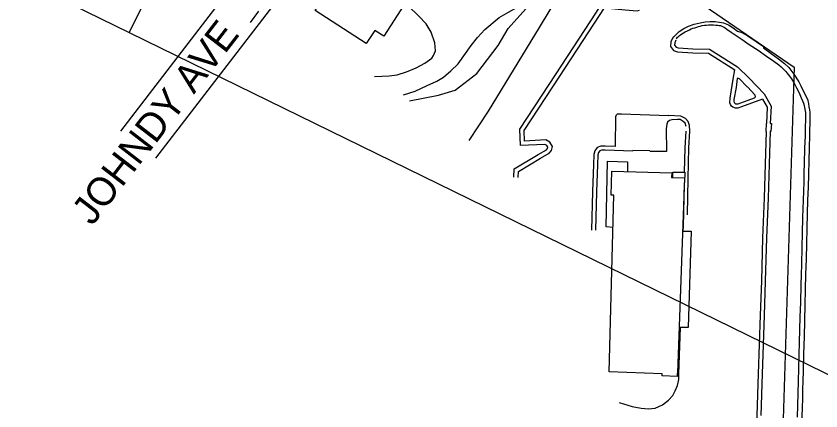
# Model space of a CAD drawing. Extents: x 1517485 to 1521905, y 636528 to 640355.
# Drawn here: x 1519953.2 to 1520407.4, y 637322.6 to 637545.3 of the extents above; entities that cross this region are included whole.
import ezdxf

# ---------------------------------------------------------------- set-up
doc = ezdxf.new("R2010")
doc.units = 0
for name, color, linetype in [('Exist Building', 7, 'Continuous'), ('Exist Building Metal Canopy', 7, 'Continuous'), ('Exist Other Culture Area Outline', 7, 'Continuous'), ('Exist Right of Way Line', 7, 'Continuous'), ('Exist Roads Change in Surface', 7, 'Continuous'), ('Exist Roads Curbs', 7, 'Continuous'), ('Exist Roads EOP', 7, 'Continuous'), ('Exist Roads EOP Other', 7, 'Continuous'), ('Exist Roads EOP Text', 7, 'Continuous'), ('Exist Roads Soil', 7, 'Continuous'), ('Exist Vegetation Woods Line', 7, 'Continuous'), ('Scratch_Level_3', 7, 'Continuous')]:
    doc.layers.add(name, color=color, linetype=linetype)

msp = doc.modelspace()

# ---------------------------------------------------------------- linework, layer by layer
at = {"layer": 'Exist Building'}
for points in [[(1520143.1, 637570.15), (1520171.98, 637551.59), (1520160.69, 637534.02), (1520155.58, 637537.3), (1520150.84, 637529.92), (1520121.89, 637548.53), (1520130.07, 637561.26), (1520135.25, 637557.94)], [(1520287.9, 637344.62), (1520290.55, 637444.38), (1520289.08, 637444.42), (1520289.44, 637457.88), (1520323.16, 637456.9), (1520323.06, 637454.35), (1520330.4, 637454.08), (1520326.36, 637344.18), (1520326.34, 637343.67), (1520326.28, 637342.06), (1520317.73, 637342.38), (1520317.77, 637343.53)]]:
    msp.add_lwpolyline(points, close=True, dxfattribs=at)
at = {"layer": 'Exist Building Metal Canopy'}
for points in [[(1520323.9, 637454.32), (1520323.9, 637457.34), (1520330.6, 637457.25), (1520330.46, 637451.24), (1520330.3, 637451.24)], [(1520329.3, 637424.1), (1520334.13, 637424.11), (1520332.4, 637369.78), (1520327.3, 637369.72)]]:
    msp.add_lwpolyline(points, dxfattribs=at)
at = {"layer": 'Exist Other Culture Area Outline'}
msp.add_lwpolyline([(1520290.07, 637426.12), (1520286.11, 637426.52), (1520286.85, 637463.46), (1520298.27, 637463.2), (1520298.22, 637457.63)], dxfattribs=at)
at = {"layer": 'Exist Right of Way Line'}
for p, q in [((1520138.34, 637644.64), (1520012.02, 637480.39)), ((1520158.15, 637629.4), (1520031.83, 637465.15)), ((1520245.65, 637617.28), (1520392.38, 637516.53)), ((1520392.38, 637516.53), (1520383.93, 637249.27))]:
    msp.add_line(p, q, dxfattribs=at)
at = {"layer": 'Exist Roads Change in Surface'}
msp.add_lwpolyline([(1520291.41, 637471.78), (1520291.7, 637488.65), (1520292.02, 637489.56), (1520292.53, 637490.21), (1520294.79, 637490.22), (1520321.33, 637489.25)], dxfattribs=at)
at = {"layer": 'Exist Roads Curbs'}
for points in [[(1520234.02, 637454.46), (1520234.33, 637459.2), (1520247.91, 637467.24), (1520252.43, 637469.91), (1520253.01, 637470.68), (1520253.22, 637471.48), (1520252.65, 637472.39), (1520251.6, 637472.97), (1520237.79, 637472.27), (1520237.48, 637481.58), (1520254.01, 637506.71), (1520267.89, 637527.96), (1520280.3, 637547.04), (1520283.92, 637552.69), (1520297.21, 637551.26), (1520303.37, 637550.74), (1520303.81, 637550.9)], [(1520325.69, 637532.47), (1520326.04, 637532.92), (1520326.47, 637533.4), (1520326.96, 637533.86), (1520327.53, 637534.33), (1520328.17, 637534.81), (1520328.89, 637535.32), (1520329.78, 637535.86), (1520330.85, 637536.44), (1520332, 637537.05), (1520333.2, 637537.67), (1520334.24, 637538.15), (1520335.15, 637538.48), (1520336.16, 637538.82), (1520337.29, 637539.18), (1520338.33, 637539.49), (1520339.29, 637539.75), (1520340.39, 637539.97), (1520341.63, 637540.16), (1520342.81, 637540.29), (1520343.9, 637540.37), (1520344.85, 637540.42), (1520345.72, 637540.43), (1520346.8, 637540.39), (1520348.07, 637540.29), (1520349.18, 637540.18), (1520350.05, 637540.07), (1520350.69, 637539.98), (1520351.14, 637539.89), (1520351.53, 637539.76), (1520351.91, 637539.57), (1520352.26, 637539.35), (1520352.76, 637539.02), (1520354.25, 637538.02), (1520356.77, 637536.33), (1520359.64, 637534.39), (1520362.85, 637532.22), (1520366.97, 637529.42), (1520371.91, 637526.05), (1520376.64, 637522.8), (1520380.83, 637519.88), (1520383.57, 637517.88), (1520384.91, 637516.76), (1520385.94, 637515.81), (1520386.84, 637514.9), (1520387.6, 637514.09), (1520388.24, 637513.35), (1520388.93, 637512.48), (1520389.71, 637511.41), (1520390.69, 637509.95), (1520391.83, 637508.13), (1520392.81, 637506.43), (1520393.62, 637504.87), (1520394.5, 637503.11), (1520395.47, 637501.14), (1520396.3, 637499.3), (1520396.96, 637497.64), (1520397.49, 637496.21), (1520397.89, 637494.98), (1520398.19, 637493.86), (1520398.4, 637492.84), (1520398.55, 637491.88), (1520398.64, 637490.97), (1520398.68, 637490.01), (1520398.67, 637488.86), (1520398.63, 637486.56), (1520398.55, 637482.94), (1520398.41, 637477.73), (1520398.21, 637470.87), (1520397.97, 637462.14), (1520397.82, 637457.06), (1520397.67, 637451.78), (1520397.52, 637446.59), (1520397.37, 637441.5), (1520397.07, 637431.68), (1520396.82, 637422.98), (1520396.63, 637415.06), (1520396.38, 637405.29), (1520396.23, 637399.54), (1520396.08, 637393.77), (1520395.8, 637383.77), (1520395.55, 637375.66), (1520395.31, 637368.33), (1520395.09, 637361.45), (1520394.9, 637354.23), (1520394.72, 637346.64), (1520394.53, 637339.37), (1520394.31, 637332.51), (1520394.12, 637325.81), (1520393.95, 637319.11)], [(1520325.44, 637531.68), (1520324.85, 637530.3), (1520324.8, 637528.94), (1520325.65, 637527.87), (1520326.86, 637527.4), (1520335.14, 637526.86), (1520344.57, 637526.63), (1520360.24, 637516.72), (1520366.98, 637510.25), (1520375.31, 637501.42), (1520379.27, 637494.52), (1520378.8, 637484.69), (1520379.44, 637484.69), (1520379.18, 637480.33), (1520378.8, 637480.4), (1520378.19, 637461.81), (1520377.57, 637442.72), (1520376.65, 637420.26), (1520375.97, 637395.89), (1520375.34, 637376.51), (1520374.17, 637343.49), (1520373.49, 637319.99)], [(1520365.75, 637505.42), (1520361.51, 637510.01), (1520360.88, 637510.19), (1520360.07, 637510.08), (1520359.52, 637505.15), (1520358.3, 637498.21), (1520358.15, 637497.38), (1520358.37, 637496.64), (1520359.26, 637495.91), (1520360.73, 637495.86), (1520369.97, 637499.25), (1520370.56, 637499.88), (1520370.36, 637500.75), (1520365.9, 637505.37)], [(1520331.33, 637483.05), (1520330.69, 637484.91), (1520329.67, 637485.97), (1520327.86, 637486.93), (1520326.51, 637487), (1520323.17, 637486.84), (1520321.99, 637486.47), (1520320.88, 637485.51), (1520320.38, 637484.47), (1520320.12, 637481.69), (1520320.24, 637468.93), (1520310.88, 637469.03)], [(1520330.49, 637457.25), (1520330.75, 637471.12), (1520331.42, 637480.5)], [(1520301.24, 637469.18), (1520285.59, 637469.71), (1520283.53, 637469.68), (1520282.56, 637469.34), (1520281.87, 637468.37), (1520281.52, 637467.03), (1520281.28, 637461.53), (1520280.78, 637446.31), (1520280.1, 637424.55)], [(1520329.72, 637424.1), (1520329.8, 637426.72), (1520330.37, 637451.24)], [(1520293.54, 637327.47), (1520300.78, 637325.11), (1520305.9, 637324.16), (1520310.09, 637323.86), (1520313.93, 637324.28), (1520317.91, 637326.1), (1520321.34, 637328.73), (1520323.84, 637331.38), (1520325.22, 637333.93), (1520326.48, 637336.94), (1520327.15, 637340.35), (1520327.27, 637343.42), (1520328.07, 637369.73)]]:
    msp.add_lwpolyline(points, dxfattribs=at)
at = {"layer": 'Exist Roads EOP'}
for points in [[(1520085.56, 637541.74), (1520090.18, 637548.04)], [(1520324.3, 637533.74), (1520327.43, 637536.57), (1520330.06, 637538.38), (1520332.68, 637539.72), (1520335.76, 637540.75), (1520339.2, 637541.64), (1520342.14, 637542.2), (1520344.94, 637542.35), (1520347.73, 637542.25), (1520350.19, 637541.95), (1520352.41, 637541.49), (1520354.36, 637540.85), (1520355.32, 637540.39), (1520357.81, 637538.73), (1520360.37, 637536.94), (1520362.77, 637536.04), (1520366.05, 637534.17), (1520370.8, 637531.06), (1520375.06, 637528.19), (1520374.92, 637527.46), (1520379.24, 637524.33), (1520383.49, 637521.25), (1520386.84, 637518.64), (1520389.37, 637516.26), (1520392.16, 637512.55), (1520394.83, 637508.25), (1520396, 637506.06), (1520397.46, 637503.14), (1520399.39, 637499.16), (1520399.91, 637497.93), (1520400.06, 637497.46), (1520400.29, 637496.01), (1520400.65, 637494.25), (1520401, 637492.55), (1520401.19, 637491.03), (1520401.19, 637487.81), (1520401.01, 637478.22), (1520400.79, 637471.07), (1520400.56, 637463.67), (1520400.34, 637456.23), (1520400.11, 637448.88), (1520399.88, 637441.54), (1520399.65, 637433.82), (1520399.44, 637425.65), (1520399.21, 637417.11), (1520398.98, 637408.28), (1520398.75, 637399.58), (1520398.52, 637391.04), (1520398.3, 637382.39), (1520398.09, 637373.57), (1520397.85, 637364.38), (1520397.58, 637354.8), (1520397.3, 637344.85), (1520397.17, 637339.74), (1520397.03, 637334.61), (1520396.9, 637329.53), (1520396.77, 637324.5), (1520396.52, 637314.57)]]:
    msp.add_lwpolyline(points, dxfattribs=at)
at = {"layer": 'Exist Roads EOP Other'}
for p, q in [((1520328.41, 637488.9), (1520321.33, 637489.25)), ((1520333.5, 637480.35), (1520333.22, 637483.7)), ((1520376.57, 637480.17), (1520376.59, 637484.74)), ((1520301.25, 637469.68), (1520310.88, 637469.53))]:
    msp.add_line(p, q, dxfattribs=at)
for points in [[(1520236.48, 637454.3), (1520236.7, 637457.75), (1520249.16, 637465.12), (1520254.1, 637468.04), (1520255.27, 637469.59), (1520255.86, 637471.88), (1520254.41, 637474.23), (1520252.17, 637475.46), (1520240.16, 637474.85), (1520239.96, 637480.88), (1520256.07, 637505.36), (1520269.95, 637526.62), (1520282.37, 637545.71), (1520285.17, 637550.09), (1520296.97, 637548.81), (1520303.69, 637548.25), (1520304.97, 637548.7)], [(1520324.23, 637533.67), (1520323.54, 637532.87), (1520322.65, 637530.79), (1520322.56, 637528.2), (1520324.28, 637526.02), (1520326.38, 637525.21), (1520335.04, 637524.65), (1520343.9, 637524.43), (1520358.86, 637514.96)], [(1520374.41, 637498.53), (1520362.61, 637494.08), (1520360.43, 637493.35), (1520359.09, 637493.39), (1520357.76, 637493.95), (1520356.99, 637494.46), (1520356.33, 637495.44), (1520356.07, 637496.39), (1520356.22, 637499.06), (1520357.87, 637509.78), (1520358.86, 637514.96)], [(1520374.41, 637498.53), (1520377.03, 637493.98), (1520376.59, 637484.74)], [(1520333.22, 637483.7), (1520332.44, 637485.98), (1520330.89, 637487.58), (1520328.41, 637488.9)], [(1520332.04, 637433.25), (1520332.52, 637453.73), (1520332.84, 637471.02), (1520333.5, 637480.35)], [(1520376.57, 637480.17), (1520375.98, 637461.88), (1520375.36, 637442.8), (1520374.43, 637420.34), (1520373.76, 637395.96), (1520373.12, 637376.59), (1520371.96, 637343.56), (1520371.28, 637320.07), (1520370.26, 637291.99), (1520369.67, 637269.57), (1520357.85, 637269.82), (1520355.39, 637269.7), (1520353.16, 637267.55), (1520352.49, 637265.06), (1520352.21, 637259.8)], [(1520291.41, 637471.78), (1520285.61, 637471.98), (1520283.12, 637471.94), (1520281.13, 637471.23), (1520279.78, 637469.35), (1520279.27, 637467.37), (1520279.02, 637461.62), (1520278.52, 637446.39), (1520277.84, 637424.62)]]:
    msp.add_lwpolyline(points, dxfattribs=at)
at = {"layer": 'Exist Roads Soil'}
for points in [[(1520155.44, 637511.28), (1520163.69, 637511.68), (1520168.25, 637512.14), (1520173.44, 637513.86), (1520178.97, 637516.12), (1520183.84, 637518.8), (1520187.77, 637521.57), (1520188.83, 637523.16), (1520189.79, 637525.81), (1520189.51, 637530.29), (1520187.38, 637536.3), (1520184.55, 637540.94), (1520180.48, 637545.31), (1520174.42, 637551.21), (1520162.54, 637560.17), (1520142.19, 637573.35), (1520130.88, 637580.35)], [(1520225.81, 637544.48), (1520231.04, 637547.64), (1520235.79, 637550.12)], [(1520171.82, 637500.89), (1520178.32, 637503), (1520185.23, 637506.21), (1520190.55, 637508.61), (1520194.32, 637510.81), (1520198.58, 637514.47), (1520202.63, 637518.51), (1520209.99, 637528.71), (1520213.51, 637533.21), (1520217.76, 637537.85), (1520225.81, 637544.48)]]:
    msp.add_lwpolyline(points, dxfattribs=at)
at = {"layer": 'Exist Vegetation Woods Line'}
for points in [[(1520175.28, 637497.58), (1520191.48, 637500.66), (1520200.9, 637503.56), (1520213.11, 637513.01), (1520225.24, 637528.71), (1520230.92, 637538.42), (1520244.15, 637553.18), (1520253.02, 637566.87), (1520257.84, 637576.08), (1520263.4, 637576.04), (1520267.62, 637570.92)], [(1520267.62, 637570.92), (1520248.47, 637538.88), (1520219.56, 637491.8), (1520208.77, 637475.23)]]:
    msp.add_lwpolyline(points, dxfattribs=at)
at = {"layer": 'Scratch_Level_3'}
for p, q in [((1520770.84, 639077.45), (1520017.02, 637536.16)), ((1519081.21, 637993.84), (1520017.02, 637536.16)), ((1520017.02, 637536.16), (1520952.83, 637078.47))]:
    msp.add_line(p, q, dxfattribs=at)

# ---------------------------------------------------------------- texts
at = {"layer": 'Exist Roads EOP Text'}
msp.add_text('JOHNDY AVE', height=16, rotation=52.3464, dxfattribs=at).set_placement((1519996.14, 637426.58))

doc.saveas('drawing.dxf')
